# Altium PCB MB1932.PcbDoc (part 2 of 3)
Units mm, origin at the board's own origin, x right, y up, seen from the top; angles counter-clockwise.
Board outline 70 x 82.5 mm, 2 copper layers (Top Layer, Bottom Layer), stack 1.543 mm thick; 185 components, 150 nets, 679 pads, 649 vias.
Unrouted connection lines stored in the file: 108.
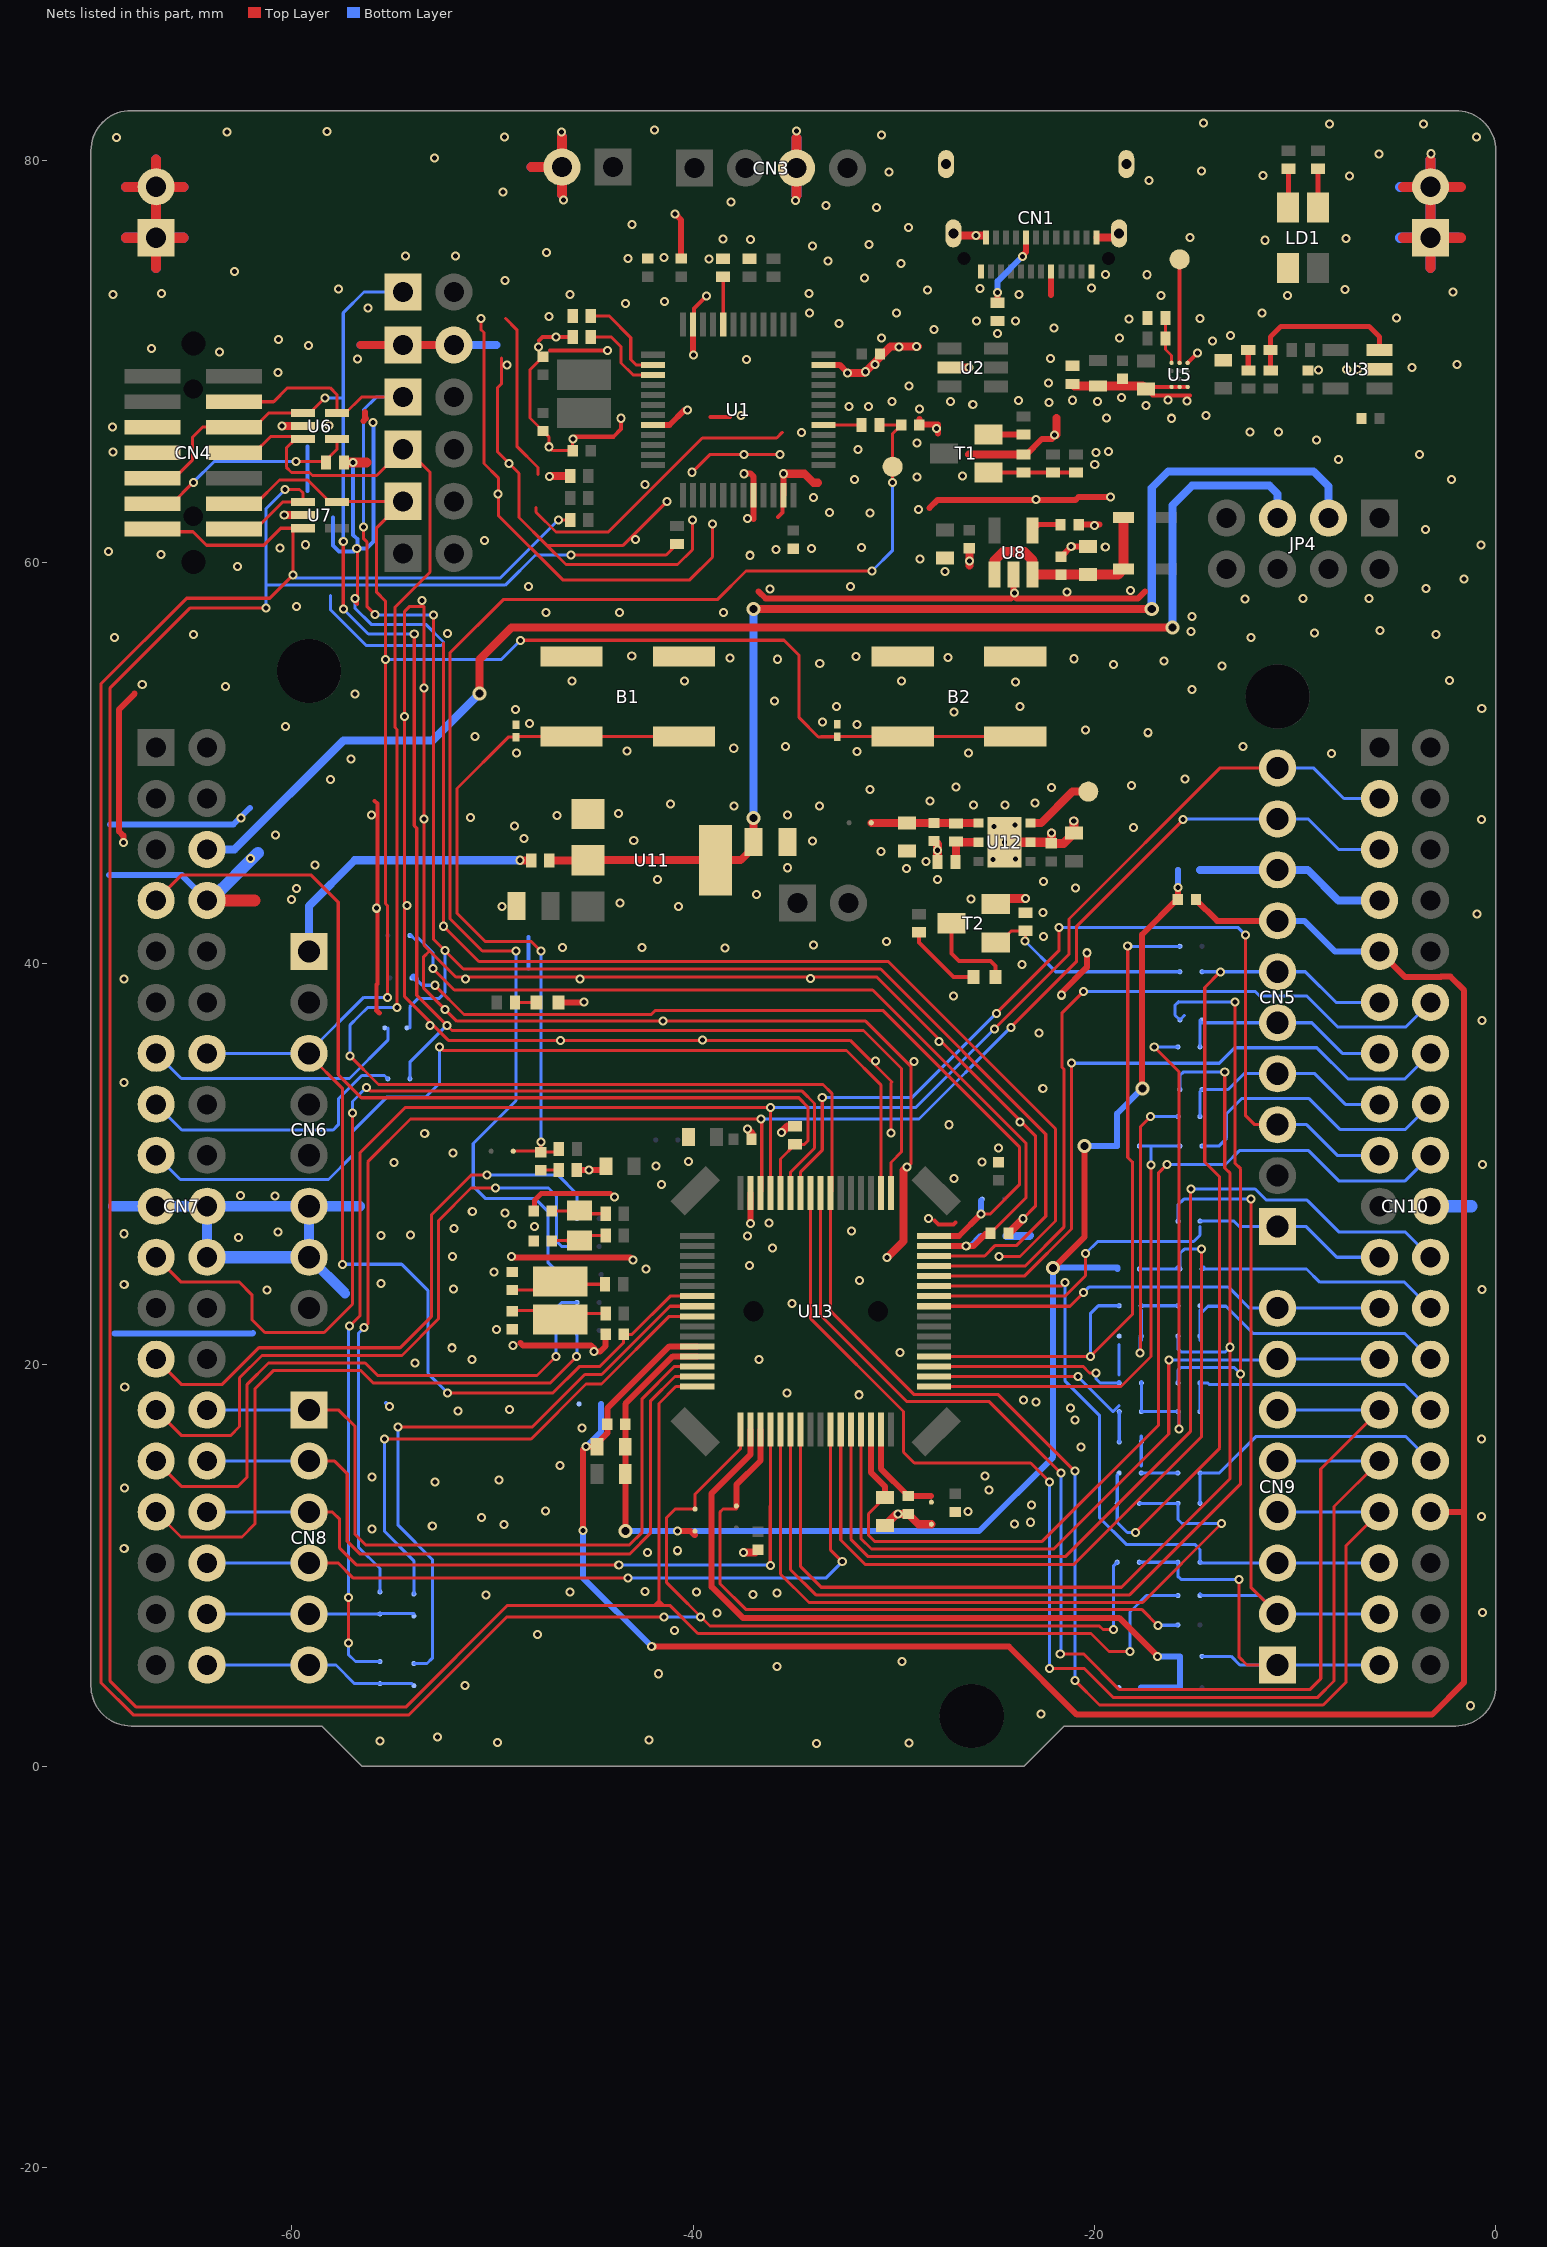
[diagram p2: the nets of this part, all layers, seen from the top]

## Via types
v1: diameter 0.45, hole 0.25, Top Layer to Bottom Layer, tented both sides, 618 vias
v2: diameter 0.7, hole 0.4, Top Layer to Bottom Layer, tented both sides, 28 vias
v3: diameter 0.5, hole 0.3, Top Layer to Bottom Layer, tented both sides, 3 vias

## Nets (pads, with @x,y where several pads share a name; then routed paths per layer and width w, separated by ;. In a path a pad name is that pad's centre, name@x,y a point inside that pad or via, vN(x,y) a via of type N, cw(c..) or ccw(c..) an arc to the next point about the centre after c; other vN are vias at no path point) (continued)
5V_VIN: C22.2 JP4.3 R26.1 U11.2 U11.4 | length 59.3
  Top Layer w0.4: R26.1@-47.165,45.139 -45.237,45.139 -45.232,45.144 U11.4@-38.887,45.144 -37.624,45.144 -36.981,45.786 C22.2@-36.981,46.043 C22.2@-36.981,46.043 v2(-36.982,47.252) ; v2(-36.981,57.666) v2(-17.141,57.666)
  Bottom Layer w0.4: v2(-36.982,47.252) v2(-36.981,57.666) v2(-36.981,57.666) ; v2(-17.141,57.666) -17.141,63.699 -16.318,64.522 -9.074,64.522 -8.33,63.777 JP4.3@-8.33,62.19
AGND: C26.1 C38.1 C39.2 CN5.7 CN10.9 CN10.32 SB36.2 U13.12 | length 116.3
  Top Layer w0.3: v1(-45.485,11.738) -45.474,11.749 -45.474,15.78 v1(-45.328,15.926) C39.2@-44.783,15.926 ; C39.2@-44.776,15.919 -44.776,16.089 -44.272,16.593 C38.1@-44.272,17.037 -44.272,17.825 -41.18,20.918 U13.12@-39.788,20.918 ; v1(-42.056,5.962) -24.266,5.962 -20.876,2.572 -3.176,2.572 -1.571,4.176 -1.571,12.66 ; C26.1@-14.941,43.181 -13.885,42.124 CN5.7@-10.87,42.124 ; CN10.9@-5.79,40.6 -4.525,39.335 -2.726,39.335 -2.721,39.34 -2.257,39.34 -1.571,38.654 -1.571,12.66 ; CN10.32@-3.25,12.66 -1.571,12.66
  Bottom Layer w0.3: v1(-45.485,11.738) -45.485,9.391 v1(-42.056,5.962) ; v1(-45.328,15.926) -44.576,16.678 SB36.2@-44.576,18.05 ; CN5.7@-10.87,42.124 -9.537,42.124 -8.013,40.6 CN10.9@-5.79,40.6
AVDD: C26.2 C38.2 C39.1 R38.2 SB8.1 SB9.2 SB21.2 SB26.2 U13.13 | length 71
  Top Layer w0.3: v2(-43.374,11.71) -43.374,14.473 -43.413,14.512 R38.2@-43.376,14.548 -43.372,14.552 C38.2@-43.372,17.037 -43.372,18.05 -41.004,20.418 U13.13@-39.788,20.418 ; v1(-40.776,11.718) -40.128,11.718 -39.92,11.509 -39.912,11.517 ; v2(-22.054,24.834) -22.023,24.834 -20.495,26.362 v2(-20.495,30.897) ; v2(-17.609,33.775) -17.62,33.786 -17.62,41.441 C26.2@-15.841,43.22 ; C26.2@-15.841,43.181 C26.2@-15.841,43.22 ; v1(-15.841,43.772) C26.2@-15.841,43.22
  Bottom Layer w0.3: v2@-43.374,11.718 v1(-40.776,11.718) -25.739,11.718 -22.055,15.402 -22.055,23.861 -22.056,23.863 -22.056,24.833 v2(-22.054,24.834) ; v2@-22.021,24.855 -18.859,24.855 SB26.2@-18.859,24.776 ; v2@-20.56,30.897 SB21.2@-18.861,30.897 -18.861,32.522 v2(-17.609,33.775) ; v2@-20.56,30.897 v2(-20.495,30.897) ; v1(-15.841,43.772) SB9.2@-15.841,44.662
BOOT0: CN7.7 R31.1 U13.60 | length 47.9
  Top Layer w0.152: CN7.7@-66.75,43.14 -65.493,44.397 -59.023,44.397 -57.677,43.051 -57.677,34.455 -56.529,33.306 -34.731,33.306 -34.275,32.85 -34.275,31.15 -34.44,30.985 R31.1@-34.91,30.985 -35.638,30.257 U13.60@-35.638,28.568
E5V: CN7.6 JP4.5 | length 66.8
  Top Layer w0.4: v2(-50.632,53.458) -50.632,55.149 -49.041,56.74 v2(-16.102,56.74)
  Bottom Layer w0.4: CN7.6@-64.21,45.68 -62.856,45.68 -57.423,51.113 -52.977,51.113 v2(-50.632,53.458) ; v2(-16.102,56.74) -16.102,62.82 -16.113,62.83 -15.127,63.816 -11.284,63.816 -10.87,63.402 JP4.5@-10.87,62.19
GND: B1.1 B1.2 B2.1 B2.2 C1.2 C2.2 C3.2 C4.1 C5.1 C6.2 C7.2 C9.1 C10.2 C11.1 C12.1 C13.1 C14.1 C15.1 C16.1 C17.2 C18.1 C19.1 C20.1 C21.1 C22.1 C23.1 C24.1 C25.1 C27.1 C28.1 C29.1 C31.2 C32.1 C33.2 C34.1 C35.1 C36.1 C37.1 C40.1 C41.2 C42.2 C43.1 CN1.A1 CN1.A12 CN1.B1 CN1.B12 CN1.SH1 CN1.SH2 CN1.SH3 CN1.SH4 CN3.3 CN4.5 CN4.7 CN6.6 CN6.7 CN7.8 CN7.19 CN7.20 CN7.22 CN10.20 JP1.2 JP2.1 JP2.2 JP3.1 JP3.2 JP11.1 JP11.2 LD1.3 LD3.2 R3.2 R4.1 R5.2 R7.2 R8.2 R9.1 R12.2 R15.1 R19.1 R21.2 R27.1 R29.2 R31.2 R33.2 SB5.2 SB6.2 SB36.1 SB54.2 T2.2 U1.8 U1.20 U1.23 U1.35 U1.47 U2.2 U3.2 U4.2 U5.A1 U5.A4 U5.B4 U5.C4 U6.2 U7.2 U8.2 U9.2 U10.2 U11.1 U12.2 U12.EP U13.63 | length 587
  Top Layer w0.152: v1(-56.85,58.192) -56.85,58.018 -56.729,57.896 v1@-56.729,60.617 ; -53.126,40.621 -53.435,40.312 -53.435,38.795 -51.765,37.125 -31.397,37.125 -29.13,34.858 -29.13,30.027 -29.297,29.86 v1(-29.338,29.86) ; -52.435,55.97 v1(-52.435,41.852) -50.674,40.092 -30.269,40.092 -21.933,31.755 -21.933,27.17 -23.705,25.398 v1(-24.757,25.398) ; v1@-50.572,72.144 v1(-50.572,72.135) -50.572,71.589 -50.418,71.435 -50.418,64.911 -49.702,64.195 -49.702,62.319 -46.496,59.113 -40.16,59.113 -39.027,60.245 v1(-39.027,61.898) ; -49.538,70.155 -49.538,68.894 -49.739,68.692 -49.739,65.494 -48.667,64.423 -48.667,62.217 -47.283,60.832 ; -49.338,72.14 -48.78,71.582 -48.78,65.769 -47.723,64.711 -47.723,64.357 ; -47.82,62.725 -47.82,62.488 -46.827,61.495 -44.219,61.495 -39.535,66.179 -35.831,66.179 -35.548,66.463 ; C4.1@-47.473,70.232 -48.12,69.584 -48.12,67.179 C10.2@-47.473,66.532 -47.182,66.242 v1(-47.182,65.745) -46.985,65.548 C13.1@-45.996,65.548 -45.996,66.119 v1(-45.98,66.135) ; v1@-47.278,64.265 v1(-47.144,64.265) ; v1(-41.287,63.023) -43.478,60.832 -47.283,60.832 ; v1(-40.04,64.475) -39.145,65.37 v1(-35.655,65.37) ; v1(-40.023,62.092) -40.023,60.62 -40.769,59.874 -46.324,59.874 -47.283,60.832 ; v1(-30.125,31.552) -30.125,34.049 -30.087,34.087 -32.168,36.167 -52.195,36.167 -54.369,38.342 -54.369,57.544 -54.116,57.796 -53.406,57.796 -53.406,40.909 -51.818,39.32 -30.84,39.32 -22.94,31.42 -22.94,27.898 v1(-23.56,27.277)
  Top Layer w0.2: -55.86,48.097 -55.722,47.96 -55.722,38.976 -55.768,38.93 ; -55.76,37.657 -55.76,38.95 ; -47.673,71.042 -47.503,71.212 R8.2@-46.118,71.212 ; -47.118,70.552 v1(-44.271,70.552) ; v1(-45.98,66.135) -45.871,66.244 -43.969,66.244 -43.588,66.625 -43.588,67.166 v1(-43.593,67.166) ; U1.47@-39.993,71.83 -39.955,71.868 -39.955,72.635 v1(-39.331,73.259) ; -39.12,67.225 -38.168,67.225 ; -35.767,62.233 -35.532,62.468 -35.532,63.291 U1.23@-35.493,63.33 ; -27.965,27.183 -27.77,26.987 -27.025,26.987 -26.925,27.087 ; C7.2@-18.601,69.131 -18.253,68.783 -18.226,68.783 ; U5.A4@-15.353,68.726 -17.534,68.726 -17.107,68.3 -15.228,68.3 ; U5.A1@-15.353,69.926 v1(-14.853,70.426)
  Top Layer w0.25: C32.1@-47.901,27.694 -47.901,28.197 -47.572,28.525 -44.103,28.525 v1@-43.945,28.368
  Top Layer w0.254: -55.76,37.657 -55.625,37.523
  Top Layer w0.3: v1(-68.387,46.017) -68.387,46.368 -68.594,46.575 -68.594,52.663 -67.818,53.439 ; -56.428,67.024 -56.299,67.152 -56.348,67.201 -56.348,67.468 ; v1(-49.033,25.395) -49.004,25.366 -48.898,25.366 -48.878,25.345 -48.872,25.351 -43.119,25.351 v1(-42.996,25.228) ; -48.607,21.095 -48.474,20.962 -45.077,20.962 -44.943,20.828 v1(-44.943,20.663) -44.625,20.663 -44.351,20.936 C37.1@-44.351,21.517 ; C32.1@-47.935,27.66 C32.1@-47.901,27.694 ; LD3.2@-46.706,38.06 v1@-45.467,38.06 ; R33.2@-45.79,29.697 -44.536,29.697 C31.2@-44.34,29.893 ; v1@-43.945,28.368 v1(-43.904,28.368) ; U1.8@-41.993,66.83 -41.173,66.83 -40.418,67.585 v1(-40.271,67.585) ; v1(-40.893,77.351) -40.588,77.046 C1.2@-40.588,75.122 ; v1@-39.993,70.328 U1.47@-39.993,71.83 ; v1@-37.457,64.415 -37.138,64.415 -36.993,64.271 -36.993,62.136 ; v1@-37.345,31.77 -37.323,31.748 v1(-37.295,31.748) ; v1(-37.138,27.03) U13.63@-37.138,28.568 ; -36.725,58.53 -36.389,58.194 -24.155,58.194 v1@-24.023,58.326 ; U1.23@-35.493,63.33 v1@-35.492,64.38 ; v1(-35.492,64.4) v1@-35.492,64.38 ; v1@-35.378,64.38 v1@-35.492,64.38 ; U1.35@-33.493,69.83 -32.697,69.83 -32.313,69.445 v1(-32.313,69.417) ; -28.726,67.131 -28.726,66.845 -27.791,66.845 -27.791,66.401 ; -28.216,62.697 -27.811,63.103 -20.93,63.103 -20.79,63.242 v1(-19.202,63.242) ; U8.2@-24.023,59.373 v1@-24.023,58.326 ; R19.1@-23.423,65.322 -22.611,66.135 -22.105,66.135 ; C19.1@-21.657,60.269 v1(-21.153,60.773) C18.1@-20.311,60.773 ; v1(-21.628,38.415) -21.628,38.55 -20.375,39.802 v1(-20.375,40.531) ; C14.1@-20.782,61.862 -19.758,61.862 ; -17.474,58.535 -17.815,58.194 -23.89,58.194 v1@-24.023,58.326
  Top Layer w0.4: v1(-60.469,66.777) U6.2@-59.438,66.777 ; v1(-60.367,62.335) U7.2@-59.438,62.334 ; -56.57,70.818 JP11.1@-54.455,70.818 JP11.2@-51.915,70.818 ; v1(-47.144,64.265) -47.144,64.278 R21.2@-46.118,64.278 ; v1(-37.484,10.643) -36.9,10.643 C43.1@-36.76,10.783 ; v1(-37.295,31.748) -37.082,31.535 C28.1@-37.082,31.24 ; v1(-35.598,31.582) -35.295,31.885 R31.2@-34.91,31.885 ; v1(-35.492,64.4) -34.45,64.4 -34.001,63.951 -33.767,63.951 ; v1(-32.313,69.417) -31.471,69.417 -30.151,70.737 v1@-28.777,70.737 ; C41.2@-30.369,11.993 C41.2@-30.438,11.993 -29.865,12.566 v1(-29.796,12.566) -29.277,12.566 -28.766,12.055 SB6.2@-28.123,12.055 ; v1(-30.324,25.345) -29.503,26.166 -29.503,29.041 -29.503,29.694 v1(-29.338,29.86) ; U2.2@-27.21,69.693 v1(-26.249,69.693) v1@-26.243,69.687 ; CN1.SH2@-27.03,76.381 -26.921,76.272 CN1.B1@-25.465,76.272 ; -26.245,65.36 R19.1@-23.54,65.36 ; v1@-26.232,59.838 C16.1@-26.232,60.683 ; C33.2@-24.28,26.55 -23.56,27.27 v1(-23.56,27.277) ; v1@-21.897,66.343 -21.897,67.168 ; CN1.B12@-19.84,76.171 -18.98,76.171 CN1.SH1@-18.77,76.381
  Top Layer w0.45: C21.1@-27.985,46.099 -27.817,45.931 R27.1@-27.817,45.055 ; T2.2@-24.914,42.952 -24.627,43.239 v1(-23.435,43.239) ; v1(-24.48,46.038) U12.2@-23.18,46.038 -22.203,46.038 C24.1@-22.148,45.984 -21.527,45.984 C23.1@-21.018,46.493 -21.018,47.093 v1(-21.028,47.102) ; C24.1@-22.143,45.989 v1(-22.143,46.508) ; R12.2@-21.087,68.878 -20.992,68.783 -18.253,68.783 ; -18.226,68.783 -17.591,68.783 C6.2@-17.534,68.726
  Top Layer w0.5: -68.261,76.16 JP2.1@-66.75,76.16 ; -68.261,78.7 JP2.2@-66.75,78.7 ; -66.75,74.649 JP2.1@-66.75,76.16 ; -66.75,80.062 JP2.2@-66.75,78.7 ; -65.388,76.16 JP2.1@-66.75,76.16 ; -65.388,78.7 JP2.2@-66.75,78.7 ; R15.1@-57.392,64.955 -56.275,64.955 ; -48.044,79.68 JP1.2@-46.533,79.68 ; -46.533,78.317 JP1.2@-46.533,79.68 ; -46.533,81.191 JP1.2@-46.533,79.68 ; -34.84,78.267 -34.84,81.141 ; -4.612,76.16 JP3.1@-3.25,76.16 ; -4.612,78.7 JP3.2@-3.25,78.7 ; -3.25,74.649 JP3.1@-3.25,76.16 ; -3.25,80.062 JP3.2@-3.25,78.7 ; -1.739,76.16 JP3.1@-3.25,76.16 ; -1.739,78.7 JP3.2@-3.25,78.7 ; JP2.1@-66.75,76.16 JP2.2@-66.75,78.7 ; JP3.1@-3.25,76.16 JP3.2@-3.25,78.7
  Top Layer w0.6: CN7.8@-64.21,43.14 -61.856,43.14
  Bottom Layer w0.152: -58.063,58.335 -58.063,57.62 -56.287,55.845 -52.56,55.845 -52.435,55.97 -52.435,56.018 -53.316,56.899 -56.036,56.899 -56.85,57.712 v1(-56.85,58.192)
  Bottom Layer w0.2: -59.197,63.552 -59.197,65.758 ; -57.927,62.21 -57.93,62.207 -57.93,60.824 -57.636,60.53 v1@-56.898,60.53 ; v1@-56.933,64.962 -56.933,61.353 -56.73,61.15 v1@-56.73,60.587 ; v1(-56.755,60.672) -56.278,60.672 -55.927,61.023 -55.927,66.937 v1@-55.938,66.947 ; -55.294,18.095 v1(-55.114,17.915) ; -48.2,39.746 -48.2,41.329
  Bottom Layer w0.254: -62.735,44.45 -62.669,44.516
  Bottom Layer w0.3: -69.092,44.4 -65.47,44.4 CN7.8@-64.21,43.14 ; -69.05,46.93 -69.047,46.933 -62.895,46.933 -62.081,47.746 ; -68.831,21.567 -61.94,21.567 -61.933,21.575 ; v1@-37.34,31.77 -37.317,31.748 v1(-37.295,31.748)
  Bottom Layer w0.4: -56.57,70.818 JP11.1@-54.455,70.818 JP11.2@-51.915,70.818 -49.8,70.818 ; SB5.2@-24.387,26.422 -23.235,26.422 -23.213,26.445
  Bottom Layer w0.5: -68.891,27.9 CN7.20@-64.21,27.9 ; -68.261,76.16 JP2.1@-66.75,76.16 ; -68.261,78.7 JP2.2@-66.75,78.7 ; -66.75,74.649 JP2.1@-66.75,76.16 ; -66.75,80.062 JP2.2@-66.75,78.7 ; -65.388,76.16 JP2.1@-66.75,76.16 ; -65.388,78.7 JP2.2@-66.75,78.7 ; CN7.22@-64.21,25.36 CN7.20@-64.21,27.9 ; -57.334,23.564 CN6.7@-59.13,25.36 CN6.6@-59.13,27.9 ; -56.59,27.9 CN6.6@-59.13,27.9 ; -48.044,79.68 JP1.2@-46.533,79.68 ; -46.533,78.317 JP1.2@-46.533,79.68 ; -46.533,81.191 JP1.2@-46.533,79.68 ; -34.84,78.267 -34.84,81.141 ; -4.761,76.16 JP3.1@-3.25,76.16 ; -4.761,78.7 JP3.2@-3.25,78.7 ; -3.25,74.649 JP3.1@-3.25,76.16 ; -3.25,80.062 JP3.2@-3.25,78.7 ; -1.888,76.16 JP3.1@-3.25,76.16 ; -1.888,78.7 JP3.2@-3.25,78.7 ; JP2.1@-66.75,76.16 JP2.2@-66.75,78.7 ; CN7.20@-64.21,27.9 CN6.6@-59.13,27.9 ; JP3.1@-3.25,76.16 JP3.2@-3.25,78.7
  Bottom Layer w0.6: CN7.22@-64.21,25.36 CN6.7@-59.13,25.36 ; CN7.8@-64.21,43.14 -64.045,43.14 -62.735,44.45 ; -62.669,44.516 -61.678,45.507 ; CN10.20@-3.25,27.9 -1.205,27.9
  other v1: -33.847,1.118 -49.74,1.169 -29.237,1.164 -55.585,1.248 -42.193,1.314 -52.729,1.459 -22.656,2.607 -1.266,3.011 -51.373,4.028 -41.729,4.606 -35.805,4.976 -29.595,5.225 -47.759,6.564 -40.918,6.749 -38.802,7.631 -0.669,7.661 -50.316,8.527 -37.014,8.545 -35.823,8.629 -39.821,8.672 -46.125,8.69 -42.391,8.693 -42.266,10.643 -40.768,10.735 -68.341,10.841 -55.991,11.814 -52.993,11.977 -49.422,12.038 -23.987,12.066 -23.178,12.155 -50.54,12.401 -0.702,12.452 -26.294,12.688 -47.35,12.718 -23.133,13.008 -25.244,13.773 -68.323,13.871 -52.867,14.165 -49.656,14.255 -55.996,14.405 -25.45,14.448 -46.626,14.982 -20.664,15.914 -0.702,16.313 -45.539,16.861 -20.974,17.26 -51.72,17.7 -49.155,17.765 -21.188,17.857 -22.9,18.157 -23.54,18.256 -31.718,18.507 -35.32,18.583 -68.316,18.893 -53.849,20.1 -36.707,20.257 -51.022,20.262 -29.684,20.623 -52.013,20.849 -48.975,20.957 -49.781,21.755 -35.079,23.051 -61.236,23.734 -0.687,23.752 -51.927,23.783 -68.341,23.998 -55.541,24.062 -31.706,24.197 -49.905,24.613 -42.342,24.776 -37.179,24.949 -51.977,25.398 -36.049,25.81 -62.638,26.335 -37.294,26.412 -55.556,26.45 -54.078,26.466 -68.346,26.53 -60.69,26.627 -32.104,26.668 -51.916,26.787 -47.907,26.902 -49.023,27.003 -36.212,27.07 -28.272,27.285 -49.369,27.555 -51,27.641 -60.828,28.407 -62.547,28.443 -41.58,28.988 -26.987,29.285 -45.19,29.697 -41.832,29.905 -0.669,29.983 -54.898,30.07 -25.6,30.105 -40.225,30.12 -51.958,30.548 -24.787,30.8 -53.368,31.528 -27.253,31.961 -23.71,32.087 -22.572,33.762 -68.346,34.056 -28.99,35.123 -30.915,35.147 -27.745,36.113 -46.605,36.165 -39.538,36.177 -22.762,36.533 -53.098,36.9 -41.485,37.143 -0.687,37.161 -52.348,37.695 -45.432,38.068 -27.019,38.38 -51.333,39.228 -45.642,39.228 -68.359,39.235 -34.135,39.238 -23.603,39.95 -38.411,40.763 -46.496,40.79 -42.546,40.783 -34.007,40.92 -30.349,41.085 -22.534,41.347 -0.931,42.459 -22.564,42.541 -55.768,42.75 -40.73,42.827 -49.515,42.843 -54.257,42.882 -43.648,43.01 -60,43.18 -26.143,43.209 -36.825,43.427 -59.751,43.734 -20.934,43.754 -22.541,44.082 -41.775,44.174 -27.817,44.174 -29.364,44.735 -35.285,44.767 -58.835,44.903 -28.399,45.073 -25.041,45.182 -23.938,45.192 -62.045,45.225 -30.641,45.576 -27.817,45.639 -34.04,46.099 -42.952,46.133 -48.41,46.226 -60.815,46.41 -18.06,46.772 -24.99,46.831 -48.898,46.859 -23.959,46.889 -0.72,47.163 -53.406,47.192 -62.515,47.258 -51.088,47.275 -56.028,47.385 -46.771,47.367 -35.292,47.403 -43.707,47.465 -37.961,47.844 -33.687,47.844 -26.013,47.892 -24.464,47.885 -41.129,47.941 -22.966,47.996 -28.201,48.085 -31.185,48.677 -26.901,48.781 -22.14,48.774 -18.142,48.858 -58.057,49.173 -15.493,49.18 -57.042,50.18 -8.175,50.458 -26.27,50.478 -48.8,50.488 -31.835,50.549 -43.28,50.585 -37.969,50.722 -12.6,50.813 -35.394,50.818 -50.868,51.303 -17.327,51.495 -20.436,51.639 -60.309,51.806 -31.835,51.913 -48.156,51.953 -33.55,52.028 -54.37,52.305 -26.985,52.523 -48.847,52.654 -0.697,52.693 -32.859,52.81 -23.705,52.797 -35.945,53.076 -56.832,53.42 -15.139,53.648 -53.409,53.727 -63.293,53.811 -67.444,53.902 -23.941,54.026 -46.019,54.062 -40.42,54.082 -29.61,54.067 -2.295,54.108 -13.651,54.819 -19.044,54.893 -33.684,54.948 -16.542,55.06 -35.795,55.157 -21.025,55.182 -38.15,55.225 -27.294,55.235 -31.889,55.289 -43.052,55.324 -68.818,56.234 -12.199,56.231 -64.901,56.384 -2.973,56.386 -52.225,56.437 -9.031,56.467 -15.191,56.528 -5.767,56.579 -15.142,57.298 -47.317,57.497 -43.657,57.497 -38.477,57.497 -59.748,57.79 -53.511,58.075 -12.504,58.156 -9.604,58.176 -6.325,58.181 -23.992,58.461 -21.355,58.504 -18.198,58.591 -36.168,58.659 -3.476,58.672 -48.205,58.773 -32.153,58.779 -1.589,59.155 -27.446,59.536 -62.69,59.778 -26.232,60.046 -28.683,60.158 -37.164,60.338 -66.517,60.377 -69.13,60.536 -35.859,60.63 -34.102,60.67 -60.583,60.705 -31.607,60.727 -19.458,60.76 -59.303,60.862 -0.728,60.859 -50.387,61.068 -42.865,61.128 -3.509,61.618 -19.999,61.819 -37.276,62.177 -31.185,62.448 -33.21,62.475 -28.77,62.607 -22.92,63.107 -33.992,63.224 -49.715,63.382 -42.391,63.867 -31.948,64.125 -2.196,64.118 -28.837,64.24 -26.568,64.295 -37.457,64.4 -19.981,64.862 -49.157,64.912 -56.948,64.962 -7.845,65.106 -3.804,65.36 -37.447,65.37 -19.927,65.467 -68.897,65.48 -19.302,65.52 -31.788,65.617 -28.833,65.932 -8.932,66.088 -21.979,66.325 -34.586,66.465 -12.237,66.485 -10.832,66.49 -27.868,66.65 -68.915,66.73 -58.135,66.804 -55.945,66.947 -16.155,67.165 -19.395,67.182 -14.44,67.295 -37.613,67.305 -28.703,67.622 -31.257,67.755 -32.217,67.76 -17.42,67.81 -26.06,67.847 -22.263,67.947 -30.087,68.006 -27.17,67.995 -19.835,68.003 -15.388,68.033 -23.785,68.04 -21.087,68.062 -16.325,68.077 -18.655,68.21 -29.248,68.762 -22.297,68.917 -60.679,69.457 -31.407,69.483 -8.828,69.562 -7.425,69.604 -6.891,69.606 -4.184,69.685 -49.275,69.825 -30.925,69.845 -1.929,69.846 -56.713,70.11 -37.337,70.097 -22.197,70.148 -39.984,70.318 -63.606,70.463 -66.98,70.653 -47.69,70.717 -29.725,70.72 -28.857,70.737 -59.166,70.78 -14.112,71.005 -60.644,71.085 -30.605,71.16 -18.743,71.156 -46.832,71.212 -13.227,71.29 -24.825,71.385 -28,71.58 -22.01,71.657 -32.718,71.887 -25.88,72.023 -23.94,72.023 -18.286,72.118 -14.735,72.134 -4.953,72.169 -47.169,72.231 -29.857,72.402 -34.198,72.418 -11.651,72.415 -56.197,72.658 -43.367,72.894 -41.419,72.988 -16.692,73.29 -10.37,73.287 -68.901,73.33 -46.125,73.33 -23.753,73.337 -66.476,73.386 -34.228,73.386 -2.12,73.466 -28.323,73.562 -7.507,73.582 -57.665,73.608 -25.692,73.638 -20.15,73.66 -49.368,74.03 -31.445,74.16 -19.45,74.317 -17.38,74.316 -62.836,74.489 -29.63,74.868 -33.275,74.994 -43.237,75.119 -39.205,75.11 -41.457,75.172 -51.84,75.243 -54.325,75.253 -47.289,75.413 -34.04,75.745 -31.23,75.835 -11.508,76.036 -37.144,76.084 -38.495,76.096 -7.459,76.117 -15.234,76.173 -25.887,76.272 -29.268,76.68 -43.047,76.825 -30.86,77.658 -33.383,77.772 -38.099,77.943 -46.45,78.042 -34.893,78.027 -49.468,78.446 -17.281,79.012 -11.586,79.256 -7.286,79.241 -30.245,79.433 -14.655,79.477 -52.88,80.132 -5.828,80.343 -3.226,80.345 -68.736,81.161 -49.394,81.169 -0.964,81.187 -30.598,81.283 -63.222,81.438 -58.248,81.442 -46.549,81.428 -34.84,81.471 -41.929,81.522 -8.292,81.822 -3.596,81.837 -14.553,81.867
GNDDetect: CN4.11 R15.2 U6.4 | length 10.9
  Top Layer w0.152: CN4.11@-66.928,62.909 -65.961,62.909 v1(-64.9,63.97) ; v1(-59.785,65) -58.432,65 -58.395,64.962 -57.738,65.62 U6.4@-57.738,66.127
  Bottom Layer w0.152: v1(-64.9,63.97) -63.87,65 v1(-59.785,65)
MCU.MCO: C11.2 R17.2 SB27.1 TP2.1 | length 70.1
  Top Layer w0.152: v1(-48.817,40.615) -50.5,40.615 -52.105,42.22 -52.105,55.48 -49.462,58.123 -38.792,58.123 -37.359,59.556 v1(-31.078,59.556) ; R17.2@-30.705,66.83 -30.702,66.833 C11.2@-29.625,66.833 -29.625,66.823 -30.055,66.393 v1@-30.055,63.967
  Bottom Layer w0.152: v1(-48.817,40.615) -48.817,33.165 -50.951,31.031 -50.951,28.895 -50.332,28.276 -47.86,28.276 -47.235,27.651 -47.235,25.11 -46.626,24.5 SB27.1@-45.676,24.5 ; v1(-31.078,59.556) -30.049,60.586 -30.063,60.599 v1(-30.063,63.967)
MCU.VCP_RX: CN4.13 R23.2 SB8.2 SB45.2 U7.3 U13.17 | length 156.2
  Top Layer w0.152: CN4.13@-66.928,61.639 -66.798,61.509 -64.911,61.509 -64.239,60.838 -61.39,60.838 -60.544,61.684 U7.3@-59.773,61.684 ; U7.3@-59.438,61.684 U7.3@-59.773,61.684 ; v1(-46.707,62.102) R23.2@-46.117,62.102 ; v1(-41.444,7.43) -49.282,7.43 -54.154,2.559 -67.899,2.559 -69.506,4.166 -69.506,53.925 -65.233,58.198 -61.09,58.198 v1(-59.942,59.345) -59.942,61.515 U7.3@-59.773,61.684 ; U13.17@-37.638,16.768 -37.638,15.813 -39.9,13.552 SB8.2@-39.9,12.81 -40.89,12.81 -41.312,12.388 -41.312,9.145 -39.154,6.987 -19.75,6.987 -19.571,6.808 v1(-19.036,6.808)
  Bottom Layer w0.152: v1(-59.942,59.345) -59.804,59.206 -49.603,59.206 v1(-46.707,62.102) ; v1(-41.444,7.43) v1(-39.628,7.43) ; v1(-19.036,6.808) -19.036,9.986 SB45.2@-18.863,10.16
MCU.VCP_TX: CN4.14 R24.2 SB48.2 U7.1 U13.16 | length 164
  Top Layer w0.152: CN4.14@-62.864,61.639 -61.796,61.639 -60.451,62.984 U7.1@-59.438,62.984 -59.438,63.447 -59.604,63.614 -59.605,63.612 v1(-60.323,63.612) ; v1(-61.269,57.718) -65.05,57.718 -69.06,53.707 -69.06,4.259 -67.741,2.94 -54.311,2.94 -49.239,8.012 -41.16,8.012 -39.758,6.61 -20.172,6.61 -19.275,5.713 v1(-18.221,5.713) ; v1(-46.085,60.353) -41.337,60.353 R24.2@-40.79,60.9 ; -41.918,8.022 -41.698,8.242 ; -41.698,8.032 -41.698,8.242 ; -41.478,8.022 -41.698,8.242 ; U13.16@-39.788,18.918 -40.856,18.918 -41.698,18.075 -41.698,8.242
  Bottom Layer w0.152: v1(-61.269,57.718) -61.269,58.847 ; v1(-60.323,63.612) -61.269,62.666 -61.269,58.847 ; v1(-46.085,60.353) -47.853,60.353 -49.358,58.847 -52.37,58.847 -52.373,58.85 -53.052,58.85 -53.055,58.847 -61.269,58.847 ; v1(-18.221,5.713) -18.221,7.687 -17.408,8.499 SB48.2@-15.839,8.499
NetB1_3: B1.3 B1.4 C30.2 R32.1 SB3.1 U10.1 | length 35.9
  Top Layer w0.152: U10.1@-48.819,51.275 -49.207,51.275 -51.764,48.718 -51.764,42.501 -50.356,41.094 -48.059,41.094 v1(-47.58,40.615) ; U10.1@-48.794,51.3 B1.4@-40.455,51.3 ; -48.782,30.647 C30.2@-47.641,30.647 ; v1(-47.586,31.1) -47.586,30.647 C30.2@-47.641,30.647 ; R32.1@-46.685,30.76 -46.848,30.597 C30.2@-47.591,30.597 C30.2@-47.641,30.647 ; R32.1@-46.685,30.76 R32.1@-46.684,30.966
  Bottom Layer w0.152: v1(-47.586,31.1) -47.588,31.103 -47.58,31.111 v1(-47.58,40.615)
NetC14_2: C14.2 U8.4 | length 1.5
  Top Layer w0.254: U8.4@-23.073,61.573 -22.783,61.862 C14.2@-21.682,61.862
NetC18_2: C18.2 C19.2 D1.2 D2.2 U8.1 U8.3 | length 10.9
  Top Layer w0.5: U8.1@-24.973,59.373 -24.972,60.071 -24.549,60.495 -23.493,60.495 -23.073,60.074 U8.3@-23.073,59.373 -23.069,59.369 C19.2@-21.657,59.369 -21.653,59.373 -18.821,59.373 D2.2@-18.544,59.65 D1.2@-18.544,62.215
NetC20_2: C20.2 C21.2 R25.2 SB1.1 U12.4 | length 5.3
  Top Layer w0.4: SB1.1@-31.102,46.991 C20.2@-29.335,46.991 ; C20.2@-29.327,46.999 C21.2@-27.985,46.999 -25.791,46.999 U12.4@-25.78,46.988
  Top Layer w0.5: C20.2@-29.335,46.991 C20.2@-29.327,46.999
NetC30_1: C30.1 R33.1 | length 0.9
  Top Layer w0.152: C30.1@-47.591,29.697 R33.1@-46.69,29.697
NetC32_2: C32.2 R34.1 X2.2 | length 2.8
  Top Layer w0.152: C32.2@-47.035,27.66 -45.703,27.66 X2.2@-45.665,27.697 -45.494,27.527 R34.1@-44.348,27.527
NetC33_1: C33.1 SB5.1 SB10.1 U13.47 | length 45
  Top Layer w0.152: v1(-52.955,39.74) -51.895,38.68 -31.047,38.68 -23.397,31.03 -23.397,28.332 C33.1@-25.18,26.55 C33.1@-25.382,26.55
  Top Layer w0.3: U13.47@-27.988,25.918 -26.015,25.918 C33.1@-25.382,26.55
  Bottom Layer w0.152: SB10.1@-54.088,41.425 -53.803,41.139 -53.682,41.26 -52.955,40.532 v1(-52.955,39.74)
  Bottom Layer w0.3: v1(-26.385,25.917) -26.16,25.917 -25.655,26.422 SB5.1@-25.487,26.422
NetC34_2: C34.2 R35.1 X2.1 | length 3.2
  Top Layer w0.152: C34.2@-47.035,26.173 -47.011,26.197 X2.1@-46.287,26.197 ; -46.311,26.173 X2.1@-46.287,26.197 ; X2.1@-46.044,26.441 X2.1@-46.287,26.197 ; R35.1@-44.348,26.441 -45.422,26.441 X2.1@-45.665,26.197 X2.1@-46.287,26.197
NetC35_2: C35.2 R36.1 X3.2 | length 4.9
  Top Layer w0.152: C35.2@-49.004,23.73 -47.035,23.73 X3.2@-46.615,24.15 -46.478,24.013 R36.1@-44.38,24.013
NetC36_2: C36.2 R37.1 X3.1 | length 5
  Top Layer w0.152: C36.2@-49.004,22.7 -47.064,22.7 X3.1@-46.615,22.25 -46.3,22.565 R37.1@-44.348,22.565
NetC42_1: C42.1 SB6.1 U13.31 | length 5
  Top Layer w0.3: U13.31@-30.638,16.768 -30.638,14.827 C42.1@-29.271,13.46 -28.156,13.46 -28.147,13.451
NetCN1_A5: CN1.A5 R12.1 | length 1.2
  Top Layer w0.3: -22.15,73.31 CN1.A5@-22.15,74.471
NetCN1_B5: CN1.B5 R3.1 | length 3.9
  Top Layer w0.3: R3.1@-24.833,72.917 -24.823,72.927 v1(-24.823,73.435) ; v1(-23.584,75.231) -23.587,75.234 -23.587,75.27 -23.4,75.457 CN1.B5@-23.4,76.171
  Bottom Layer w0.3: v1(-24.823,73.435) -24.823,73.992 v1(-23.584,75.231) v1@-23.604,75.231
NetCN5_4: CN5.4 CN10.15 SB18.2 SB19.1 | length 11.2
  Bottom Layer w0.152: SB19.1@-14.739,32.37 -14.739,33.617 SB18.2@-14.639,33.717 -13.334,33.717 -12.546,34.504 CN5.4@-10.87,34.504 -9.016,34.504 -7.492,32.98 CN10.15@-5.79,32.98
NetCN5_5: CN5.5 CN10.13 SB14.2 SB16.1 | length 10.8
  Bottom Layer w0.152: SB16.1@-14.737,35.837 SB14.2@-14.737,37.184 ; -14.637,37.044 CN5.5@-10.87,37.044 -9.168,37.044 -7.644,35.52 CN10.13@-5.79,35.52
NetCN5_6: CN5.6 CN10.11 SB12.2 SB41.1 SB43.2 | length 43.3
  Top Layer w0.152: v1(-17.962,11.641) -13.756,15.848 -13.756,29.358 -14.5,30.102 -14.5,38.804 v1(-13.725,39.579)
  Bottom Layer w0.152: -18.861,14.513 -18.861,12.145 -18.357,11.641 v1(-17.962,11.641) ; SB12.2@-14.64,39.584 CN5.6@-10.87,39.584 -9.488,39.584 -7.964,38.06 CN10.11@-5.79,38.06
NetCN5_8: CN5.8 CN10.7 SB9.1 | length 9.6
  Bottom Layer w0.4: SB9.1@-14.739,44.664 CN5.8@-10.87,44.664 -9.369,44.664 -7.845,43.14 CN10.7@-5.79,43.14
NetCN6_1: CN6.1 R26.2 | length 14.3
  Top Layer w0.4: v1(-48.629,45.141) -48.626,45.139 R26.2@-48.065,45.139
  Bottom Layer w0.4: CN6.1@-59.13,40.6 -59.13,42.868 -56.857,45.142 v1(-48.629,45.141)
NetCN7_13: CN7.13 SB15.2 | length 13.5
  Bottom Layer w0.152: CN7.13@-66.75,35.52 -65.498,34.268 -57.117,34.268 -55.209,36.176 -55.209,36.79
NetCN7_15: CN7.15 SB17.2 | length 14
  Bottom Layer w0.152: CN7.15@-66.75,32.98 -65.47,31.7 -57.933,31.7 -57.675,31.958 -57.675,33.244 -56.504,34.415 -55.374,34.415 SB17.2@-55.209,34.25
NetCN7_25: CN7.25 SB22.2 | length 30.4
  Top Layer w0.152: CN7.25@-66.75,20.28 -65.478,19.007 -63.476,19.007 -61.636,20.848 -54.591,20.848 -53.04,22.399 -53.04,27.46 -51.037,29.462 v1(-50.263,29.462)
  Bottom Layer w0.152: v1(-50.263,29.462) -46.745,29.462 -45.776,28.493 SB22.2@-45.776,27.283
NetCN7_27: CN7.27 SB24.2 | length 33.4
  Top Layer w0.152: CN7.27@-66.75,17.74 -65.48,16.47 -63.047,16.47 -62.595,16.922 -62.595,19.35 -61.478,20.467 -54.505,20.467 -52.685,22.287 -52.685,27.18 -51.058,28.807 v1(-49.841,28.807)
  Bottom Layer w0.152: v1(-49.841,28.807) -47.2,28.807 -46.796,28.403 -46.796,26.147 -46.54,25.891 SB24.2@-45.776,25.891
NetCN7_29: CN7.29 SB28.2 | length 29.9
  Top Layer w0.152: CN7.29@-66.75,15.2 -65.493,13.943 -62.676,13.943 -62.214,14.405 -62.214,19.026 -61.153,20.087 -56.338,20.087 -55.716,19.465 -47.774,19.465 v1(-46.829,20.41)
  Bottom Layer w0.152: v1(-46.829,20.41) -46.829,22.82 -46.541,23.108 SB28.2@-45.776,23.108
NetCN7_31: CN7.31 SB31.2 | length 31
  Top Layer w0.152: CN7.31@-66.75,12.66 -65.513,11.423 -62.473,11.423 -61.833,12.063 -61.833,18.794 -60.921,19.706 -56.542,19.706 -55.92,19.084 -47.124,19.084 v1(-45.798,20.41)
  Bottom Layer w0.152: v1(-45.798,20.41) -45.785,20.422 -45.785,21.479 -45.8,21.494 -45.8,21.62 -45.795,21.625 -45.795,21.697 SB31.2@-45.776,21.717
NetCN7_36: CN7.36 CN8.5 SB46.2 SB47.1 | length 10.3
  Bottom Layer w0.152: CN7.36@-64.21,7.58 CN8.5@-59.13,7.58 SB47.1@-55.602,7.58 ; SB47.1@-55.599,7.583 -55.585,7.597 SB46.2@-53.898,7.597
NetCN7_38: CN7.38 CN8.6 SB51.1 SB52.2 | length 10.6
  Bottom Layer w0.152: CN7.38@-64.21,5.04 CN8.6@-59.13,5.04 -57.794,5.04 -56.866,4.112 SB51.1@-55.599,4.112 -54.009,4.112
NetCN10_26: CN10.26 SB29.1 SB32.1 | length 14.3
  Bottom Layer w0.152: -14.741,21.208 -14.741,22.721 ; -14.74,22.515 -14.339,22.917 -13.441,22.917 -12.074,21.55 -4.52,21.55 CN10.26@-3.25,20.28
NetCN10_28: CN10.28 SB34.1 SB37.1 | length 13.6
  Bottom Layer w0.152: SB37.1@-14.739,17.666 SB34.1@-14.739,19.098 ; SB34.1@-14.739,19.179 SB34.1@-14.739,19.098 ; CN10.28@-3.25,17.74 -4.52,19.01 -14.256,19.01 -14.344,19.098 SB34.1@-14.739,19.098
NetCN10_30: CN10.30 SB40.1 SB42.1 | length 14.3
  Bottom Layer w0.152: SB42.1@-14.738,13.097 -14.738,14.607 SB40.1@-14.741,14.61 -13.771,14.61 -11.962,16.419 -4.469,16.419 CN10.30@-3.25,15.2
NetLD1_1: LD1.1 R1.1 | length 1.9
  Top Layer w0.254: LD1.1@-10.337,77.673 R1.1@-10.337,79.596
NetLD1_2: LD1.2 R2.2 | length 1.9
  Top Layer w0.254: LD1.2@-8.863,77.673 R2.2@-8.863,79.596
NetLD2_1: LD2.1 R13.1 | length 1
  Top Layer w0.254: R13.1@-12.332,69.554 LD2.1@-12.332,70.571
NetLD2_2: LD2.2 R14.1 U3.3 | length 8.2
  Top Layer w0.254: R14.1@-11.232,69.568 LD2.2@-11.232,70.571 -11.232,71.216 -10.704,71.745 -6.312,71.745 -5.791,71.224 U3.3@-5.791,70.556
NetLD3_1: LD3.1 R30.2 | length 1.1
  Top Layer w0.152: R30.2@-48.876,38.06 LD3.1@-47.806,38.06
NetLD4_1: LD4.1 R28.1 | length 3.9
  Top Layer w0.2: R28.1@-28.742,41.552 -28.742,41.042 -27.03,39.33 LD4.1@-26.025,39.33
NetLD4_2: LD4.2 T2.3 | length 4.5
  Top Layer w0.2: T2.3@-27.114,42.002 -27.114,40.502 -26.734,40.122 -25.175,40.122 -24.925,39.872 LD4.2@-24.925,39.33
NetR4_2: R4.2 U1.44 | length 2.4
  Top Layer w0.152: U1.44@-38.493,71.83 R4.2@-38.493,74.203
NetR7_1: R7.1 U1.2 | length 4.9
  Top Layer w0.152: R7.1@-45.218,72.268 -44.188,72.268 -43.103,71.183 -43.103,70.094 -42.838,69.83 U1.2@-41.993,69.83
NetR8_1: R8.1 U1.3 | length 4.5
  Top Layer w0.152: R8.1@-45.218,71.212 -44.068,71.212 -43.585,70.729 -43.585,69.922 -42.993,69.33 U1.3@-41.993,69.33
NetR9_2: R9.2 R10.1 U5.C1 | length 2.4
  Top Layer w0.152: R9.2@-16.452,72.17 R10.1@-16.452,71.129 -16.452,70.595 -16.153,70.295 U5.C1@-16.153,69.926
NetR16_2: R16.2 T1.2 | length 1.7
  Top Layer w0.3: T1.2@-25.284,66.366 R16.2@-23.556,66.366
NetR17_1: R17.1 U1.29 | length 2.1
  Top Layer w0.152: U1.29@-33.493,66.83 R17.1@-31.605,66.83 R17.1@-31.478,66.702
NetR18_1: R18.1 R19.2 R20.1 T1.1 | length 4.4
  Top Layer w0.203: T1.1@-25.284,64.466 -20.917,64.466 R18.1@-20.911,64.46
NetR25_1: R25.1 R27.2 U12.5 | length 2.2
  Top Layer w0.4: R27.2@-26.917,45.055 -26.905,45.067 R25.1@-26.905,46.073 -26.87,46.038 U12.5@-25.78,46.038
NetR29_1: R29.1 SB12.1 T2.1 | length 10.7
  Top Layer w0.152: T2.1@-24.914,41.052 -24.7,41.052 -24.127,41.626 R29.1@-23.443,41.626 -23.443,41.136 v1(-23.461,41.118) -23.377,41.034 v1@-23.359,41.052
  Bottom Layer w0.152: v1(-23.461,41.118) -21.927,39.584 SB12.1@-15.74,39.584
NetSB4_2: SB4.2 SB13.2 U13.48 | length 41.8
  Top Layer w0.152: v1(-52.867,38.913) -51.41,37.455 -42.08,37.455 -41.87,37.665 -30.543,37.665 -23.741,30.864 -23.741,28.968 -25.205,27.505 v1(-25.658,27.505)
  Top Layer w0.3: U13.48@-27.988,26.418 -26.745,26.418 v1(-25.658,27.505)
  Bottom Layer w0.152: -53.793,39.216 -53.49,38.913 v1(-52.867,38.913)
  Bottom Layer w0.3: SB13.2@-53.933,39.355 -53.793,39.216 ; v1(-25.658,27.505) SB4.2@-25.658,28.185
NetSB7_2: SB7.2 SB49.2 U13.19 | length 32.6
  Top Layer w0.152: SB7.2@-37.84,12.968 -37.84,12.81 -38.505,12.81 -38.665,12.651 -38.665,9.106 -37.354,7.796 -17.619,7.796 -16.837,7.014 v1(-16.829,7.021)
  Top Layer w0.3: SB7.2@-37.84,12.968 -37.84,14.024 -36.638,15.226 U13.19@-36.638,16.768
  Bottom Layer w0.152: v1(-16.829,7.021) -15.855,7.021 SB49.2@-15.84,7.036
NetSB11_1: SB11.1 SB30.1 U13.36 | length 35.5
  Top Layer w0.152: U13.36@-27.988,20.418 v1(-20.204,20.418) -18.093,22.529 -18.093,30.086 -18.108,30.101 -18.338,30.331 v1(-18.338,40.859)
  Bottom Layer w0.152: v1(-20.204,20.418) -20.204,22.544 -19.806,22.942 SB30.1@-18.763,22.942 ; v1(-18.338,40.859) -18.333,40.854 SB11.1@-15.739,40.854
NetSB20_1: SB20.1 SB21.1 U13.33 | length 23.9
  Top Layer w0.152: U13.33@-27.988,18.918 -21.037,18.918 -21.032,18.913 -20.614,18.913 -20.61,18.918 -18.677,18.918 -17.178,20.416 v1@-17.178,29.96
  Bottom Layer w0.152: SB21.1@-17.761,30.897 -17.169,30.897 ; v1(-17.179,29.96) -17.179,30.887 -17.169,30.897 ; SB20.1@-15.739,30.897 -17.169,30.897
NetSB25_1: SB25.1 SB26.1 U13.27 | length 40.1
  Top Layer w0.152: U13.27@-32.638,16.768 -32.638,11.271 -31.426,10.059 -21.012,10.059 -14.662,16.409 v1(-14.662,25.764)
  Bottom Layer w0.152: SB26.1@-17.759,24.776 -15.884,24.776 -15.917,24.809 -15.736,24.99 ; SB25.1@-15.736,24.776 -15.736,24.99 ; v1(-14.662,25.764) -15.516,25.764 -15.736,25.544 -15.736,24.99
NetSB33_1: SB33.1 SB35.1 U13.35 | length 11.3
  Top Layer w0.152: U13.35@-27.988,19.918 -27.983,19.922 -20.57,19.922 -20.24,19.592 v1(-19.915,19.592)
  Bottom Layer w0.152: v1(-19.915,19.592) -19.915,19.3 -19.713,19.098 SB35.1@-18.762,19.098 ; SB35.1@-18.791,19.15 SB35.1@-18.762,19.179 ; -18.763,19.489 -18.763,21.002
NetSB38_1: SB38.1 SB39.1 U13.34 | length 11.6
  Top Layer w0.152: U13.34@-27.988,19.418 v1(-20.823,19.418)
  Bottom Layer w0.152: v1(-20.823,19.418) -19.072,17.666 -18.763,17.976 ; SB39.1@-18.762,16.153 SB38.1@-18.762,17.666
NetSB50_1: SB50.1 SB53.1 SB54.1 U13.18 | length 36.9
  Top Layer w0.152: -37.528,7.431 -37.489,7.392
  Top Layer w0.3: U13.18@-37.138,16.768 -37.138,15.525 -39.068,13.595 -39.068,8.939 -37.544,7.415 -37.52,7.391 -18.763,7.391 v1(-16.844,5.472)
  Bottom Layer w0.3: SB54.1@-17.673,3.912 SB53.1@-15.74,3.912 SB50.1@-15.74,5.474 -15.742,5.472 v1(-16.844,5.472)
NetTP1_1: TP1.1 U5.B1 | length 5.2
  Top Layer w0.203: U5.B1@-15.753,69.926 TP1.1@-15.753,75.082
NetTP3_1: TP3.1 U12.3 | length 3.5
  Top Layer w0.4: U12.3@-23.18,46.988 -22.663,46.988 -21.089,48.563 TP3.1@-20.304,48.563
NRST: B2.3 B2.4 C37.2 CN4.12 CN6.3 CN7.14 JP9.1 U7.5 U9.1 U13.7 | length 117.6
  Top Layer w0.152: CN4.12@-62.864,62.909 -61.784,62.909 -60.602,64.091 -59.204,64.091 -58.14,63.028 JP9.1@-54.455,63.028 -55.766,61.717 -55.766,58.491 -55.325,58.05 v1(-55.325,55.153) -55.325,48.057 -55.318,48.051 -55.318,42.978 -55.23,42.89 v1(-55.23,38.31) ; CN6.3@-59.13,35.52 -59.13,35.441 -57.471,33.783 v1(-57.471,25.009) ; v1(-52.232,18.6) -46.973,18.6 -45.651,19.922 -44.636,19.922 -43.46,21.098 -43.46,21.507 C37.2@-43.451,21.517 -43.042,21.517 -41.141,23.418 U13.7@-39.788,23.418 ; v1(-48.595,56.102) -35.469,56.102 -34.713,55.346 -34.713,52.243 -33.755,51.286 U9.1@-32.821,51.286 ; -33.63,51.3 B2.4@-23.945,51.3
  Bottom Layer w0.152: CN7.14@-64.21,35.52 CN6.3@-59.13,35.52 -59.13,35.585 -56.405,38.31 v1(-55.23,38.31) ; v1(-57.471,25.009) -54.515,25.009 -53.214,23.709 -53.214,19.582 v1(-52.232,18.6) ; v1(-55.325,55.153) -49.545,55.153 v1(-48.595,56.102)
PA0: CN7.28 CN8.1 U13.14 | length 37.9
  Top Layer w0.152: CN8.1@-59.13,17.74 -57.647,17.74 -56.844,16.937 -56.844,11.553 -56.311,11.019 -43.176,11.019 -42.536,11.659 -42.536,18.315 -40.933,19.918 U13.14@-39.788,19.918
  Bottom Layer w0.152: CN7.28@-64.21,17.74 CN8.1@-59.13,17.74
PA1: CN7.30 CN8.2 U13.15 | length 35.8
  Top Layer w0.152: CN8.2@-59.13,15.2 -57.858,15.2 -57.228,14.57 -57.228,11.202 -56.588,10.562 -43.167,10.562 -42.125,11.604 -42.125,18.187 -40.895,19.418 U13.15@-39.788,19.418
  Bottom Layer w0.152: CN7.30@-64.21,15.2 CN8.2@-59.13,15.2
PA2: CN9.2 CN10.35 SB23.2 SB48.1 | length 35.2
  Top Layer w0.152: v1@-12.206,28.335 v1(-12.206,28.253) -12.206,28.206 -12.205,28.205 -12.205,8.915 CN9.2@-10.87,7.58
  Bottom Layer w0.152: SB23.2@-15.839,27.156 -15.839,27.958 -15.544,28.253 v1(-12.206,28.253) ; SB48.1@-14.74,8.598 -14.652,8.51 -11.8,8.51 CN9.2@-10.87,7.58 CN10.35@-5.79,7.58
PA3: CN9.1 CN10.37 SB44.2 SB45.1 SB50.2 | length 20.7
  Top Layer w0.152: v1(-12.803,9.297) -12.803,6.973 -12.803,5.45 -12.393,5.04 CN9.1@-10.87,5.04
  Bottom Layer w0.152: SB45.1@-17.763,10.16 SB44.2@-15.84,10.16 -15.84,9.461 -15.676,9.297 v1(-12.803,9.297) ; SB50.2@-14.64,5.474 -13.183,5.474 -12.75,5.04 CN9.1@-10.87,5.04 CN10.37@-5.79,5.04
PA4: CN7.32 CN8.3 U13.20 | length 36.8
  Top Layer w0.152: CN8.3@-59.13,12.66 -57.962,12.66 -57.609,12.307 -57.609,10.864 -56.776,10.031 v1(-43.7,10.031) ; v1(-36.148,10.003) -36.15,10.006 -36.15,12.973 -36.138,12.985 U13.20@-36.138,16.768
  Bottom Layer w0.152: CN7.32@-64.21,12.66 CN8.3@-59.13,12.66 ; v1(-43.7,10.031) -36.175,10.031 v1(-36.148,10.003)
PA5: SB42.2 SB43.1 U13.21 | length 36.4
  Top Layer w0.152: U13.21@-35.638,16.768 -35.638,9.569 -34.223,8.154 -17.596,8.154 v1(-13.662,12.088)
  Bottom Layer w0.152: SB43.1@-17.761,13.097 SB42.2@-15.838,13.097 -15.838,12.294 -15.633,12.088 v1(-13.662,12.088)
PA6: SB14.1 SB34.2 U13.22 | length 64.5
  Top Layer w0.152: U13.22@-35.138,16.768 -35.138,9.793 -33.88,8.535 -18.244,8.535 -12.712,14.067 -12.712,29.764 -13,30.052 -13,38.079 v1(-12.994,38.085)
  Bottom Layer w0.152: SB34.2@-15.839,19.098 -15.839,19.723 -15.695,19.867 -13.025,19.867 v1(-12.709,19.551) ; -15.509,37.412 SB14.1@-15.737,37.184 -15.978,37.424 -15.978,37.915 -15.803,38.09 -15.798,38.085 v1(-12.994,38.085)
PA7: SB18.1 SB32.2 U13.23 | length 57.7
  Top Layer w0.152: U13.23@-34.638,16.768 -34.638,9.941 -33.613,8.916 -18.653,8.916 -13.232,14.336 -13.232,29.538 -13.504,29.81 v1(-13.504,34.58)
  Bottom Layer w0.152: SB32.2@-15.841,21.429 -15.841,20.801 -15.669,20.629 -13.493,20.629 v1(-13.248,20.874) ; SB18.1@-15.739,33.717 -15.739,34.413 -15.572,34.58 v1(-13.504,34.58)
PA8: CN9.8 CN10.23 U13.41 | length 23
  Top Layer w0.152: U13.41@-27.988,22.918 -21.219,22.918 v1(-20.545,23.592)
  Bottom Layer w0.152: v1(-20.545,23.592) -20.253,23.884 -13.331,23.884 -12.267,22.82 CN9.8@-10.87,22.82 CN10.23@-5.79,22.82
PA9: CN5.1 CN10.21 SB23.1 U13.42 | length 25.3
  Top Layer w0.152: U13.42@-27.988,23.418 -21.461,23.418 -20.438,24.441 v1(-20.438,25.545)
  Bottom Layer w0.152: v1(-20.438,25.545) -19.839,26.145 -15.053,26.145 -14.739,26.459 -14.739,26.884 ; SB23.1@-14.739,27.156 -13.042,27.156 -12.77,26.884 CN5.1@-10.87,26.884 -9.44,26.884 -7.916,25.36 CN10.21@-5.79,25.36
PA10: CN9.3 CN10.33 SB44.1 U13.43 | length 34.3
  Top Layer w0.152: U13.43@-27.988,23.918 -21.647,23.918 v1(-21.453,24.112)
  Bottom Layer w0.152: v1(-21.453,24.112) -21.453,19.184 -19.755,17.486 -19.755,12.393 -18.414,11.052 -14.998,11.052 -14.74,10.795 SB44.1@-14.74,10.16 ; SB44.1@-14.7,10.12 CN9.3@-10.87,10.12 CN10.33@-5.79,10.12
PA11: CN10.14 U13.44 | length 35.5
  Top Layer w0.152: U13.44@-27.988,24.418 -23.492,24.418 -21.142,26.768 v1(-21.142,35.035)
  Bottom Layer w0.152: v1(-21.142,35.035) -21.132,35.025 -13.773,35.025 -12.998,35.799 -8.914,35.799 -7.365,34.25 -4.52,34.25 CN10.14@-3.25,35.52
PA12: CN10.12 U13.45 | length 38
  Top Layer w0.152: U13.45@-27.988,24.918 -23.459,24.918 -21.52,26.856 -21.52,34.736 -21.621,34.837 -21.621,37.524 v1(-20.55,38.595)
  Bottom Layer w0.152: v1(-20.55,38.595) -11.971,38.595 -11.743,38.366 -9.409,38.366 -7.883,36.841 -4.469,36.841 CN10.12@-3.25,38.06
PA13: CN4.4 JP7.1 SB15.1 U6.5 U13.46 | length 92.5
  Top Layer w0.152: CN4.4@-62.864,67.989 -60.898,67.989 -60.207,68.68 -58.081,68.68 -57.738,68.336 U6.5@-57.738,67.427 ; U6.5@-57.519,67.427 -57.312,67.427 -56.522,68.217 JP7.1@-54.455,68.217 JP7.1@-54.254,68.217 ; v1(-56.43,61.743) -56.43,61.184 -56.251,61.005 -56.251,57.791 v1(-55.838,57.378) ; U13.46@-27.988,25.418 -25.47,25.418 -24.933,25.955 -23.867,25.955 -22.423,27.4 -22.423,31.495 -30.65,39.723 -51.445,39.723 -52.927,41.205 v1(-52.927,57.36) ; v1(-52.927,57.36) -53.025,57.36 -52.927,57.457 v1(-52.927,57.36)
  Bottom Layer w0.152: v1(-56.43,61.743) -56.43,67.575 -55.788,68.217 JP7.1@-54.455,68.217 JP7.1@-54.254,68.217 ; v1@-55.838,57.36 v1(-52.927,57.36) ; -54.109,36.79 -54.109,37.836 -53.685,38.26 -52.639,38.26 -52.358,38.541 v1(-52.358,40.648)
PA14: CN4.6 CN4.9 JP6.1 SB17.1 U6.1 U13.49 | length 87.8
  Top Layer w0.152: CN4.9@-66.928,64.179 -65.856,64.179 -64.932,65.103 -64.932,66.228 -64.441,66.719 -61.853,66.719 -61.145,67.427 U6.1@-59.438,67.427 -59.096,67.427 v1(-58.348,68.175) ; v1(-57.428,61.032) -57.428,57.663 v1(-57.425,57.66) ; v1(-53.89,56.413) -53.89,46.865 -53.765,46.74 -53.765,38.415 v1(-52.268,36.918) -52.01,36.66 -31.508,36.66 -29.609,34.761 -29.609,30.611 -30.138,30.082 U13.49@-30.138,28.568
  Bottom Layer w0.152: v1(-58.348,68.175) -57.428,68.175 ; v1(-57.428,61.032) -57.428,68.174 -57.428,72.42 -56.39,73.458 JP6.1@-54.455,73.458 JP6.1@-54.255,73.458 ; v1(-57.425,57.66) -56.178,56.413 v1(-53.89,56.413) ; SB17.1@-54.109,34.25 -54.109,35.081 v1@-52.27,36.92
PA15: CN7.17 U13.50 | length 47.3
  Top Layer w0.152: v1(-52.635,35.835) -52.462,35.662 -32.353,35.662 -30.638,33.948 U13.50@-30.638,28.568
  Bottom Layer w0.152: CN7.17@-66.75,30.44 -65.546,29.236 -58.158,29.236 -56.958,30.436 -56.958,31.64 -55.263,33.335 -53.333,33.335 -52.635,34.033 v1(-52.635,35.835)
PB0: CN7.34 CN8.4 U13.26 | length 39.1
  Top Layer w0.152: CN8.4@-59.13,10.12 -57.677,10.12 -56.928,9.371 v1(-43.242,9.371) ; U13.26@-33.138,16.768 -33.138,10.762 v1(-32.563,10.187)
  Bottom Layer w0.152: CN7.34@-64.21,10.12 CN8.4@-59.13,10.12 ; v1(-43.242,9.371) -33.38,9.371 v1(-32.563,10.187)
PB1: CN10.24 SB25.2 | length 12.3
  Bottom Layer w0.152: SB25.2@-14.549,24.863 SB25.2@-14.636,24.776 -9.427,24.776 -8.767,24.115 -4.546,24.115 CN10.24@-3.25,22.82
PB2: CN10.22 U13.28 | length 50.8
  Top Layer w0.152: U13.28@-32.138,16.768 -32.138,11.309 -31.268,10.44 -21.447,10.44 -15.219,16.668 -15.219,28.725 v1(-15.186,28.759)
  Bottom Layer w0.152: v1(-15.186,28.759) -11.988,28.759 -11.449,28.22 -9.427,28.22 -9.379,28.172 -9.371,28.179 -7.801,26.609 -4.499,26.609 CN10.22@-3.25,25.36
PB3: CN4.8 CN9.4 CN10.31 JP8.1 U6.3 U13.55 | length 136
  Top Layer w0.152: CN4.8@-62.864,65.449 -61.856,65.449 -61.054,66.25 -59.7,66.25 U6.3@-59.824,66.127 ; U6.3@-59.438,66.127 U6.3@-59.824,66.127 ; v1(-57.098,35.392) -55.671,33.966 -33.518,33.966 -33.081,33.529 -33.081,28.624 U13.55@-33.138,28.568 -33.138,22.672 -28.977,18.512 -24.787,18.512 v1(-20.972,14.697) ; v1(-54.745,37.795) -54.745,51.661 -54.849,51.765 -54.849,54.952 -54.846,54.954 -54.846,55.351 -54.848,55.352 -54.848,57.755 -53.108,59.495 -53.108,64.474 -54.355,65.721 JP8.1@-54.455,65.621 -55.765,64.31 -58.957,64.31 -59.111,64.465 -60.002,64.465 -60.264,64.726 -60.264,65.687 U6.3@-59.824,66.127 ; v1(-20.972,4.278) -19.745,3.051 -8.602,3.051 -7.456,4.197 -7.456,10.994 CN10.31@-5.79,12.66
  Bottom Layer w0.152: v1(-57.098,35.392) -57.098,36.918 -56.638,37.377 -56.64,37.378 -56.222,37.796 ; -56.221,37.795 v1(-54.745,37.795) ; v1(-20.972,4.278) v1(-20.972,14.697) ; CN9.4@-10.87,12.66 CN10.31@-5.79,12.66
PB4: CN9.6 CN10.27 U13.56 | length 64
  Top Layer w0.152: U13.56@-33.638,28.568 -33.638,22.453 -29.366,18.182 -25.262,18.182 -23.128,16.048 -23.114,16.048 v1(-21.666,14.601) ; v1(-21.701,5.589) -20.53,5.589 -18.754,3.813 -9.267,3.813 -8.721,4.359 -8.721,14.809 CN10.27@-5.79,17.74
  Bottom Layer w0.152: v1(-21.701,5.589) -21.666,5.623 v1(-21.666,14.601) ; CN9.6@-10.87,17.74 CN10.27@-5.79,17.74
PB5: CN9.5 CN10.29 U13.57 | length 64.1
  Top Layer w0.152: U13.57@-34.138,28.568 -34.138,22.298 -29.514,17.674 -29.514,15.65 -28.974,15.11 -23.178,15.11 v1(-22.239,14.171) ; v1(-22.239,4.862) -20.504,4.862 -19.074,3.432 -8.866,3.432 -8.056,4.242 -8.056,12.934 CN10.29@-5.79,15.2
  Bottom Layer w0.152: v1(-22.239,4.862) v1(-22.239,14.171) ; CN9.5@-10.87,15.2 CN10.29@-5.79,15.2
PB6: CN5.3 CN10.17 U13.58 | length 47.1
  Top Layer w0.152: U13.58@-34.638,28.568 -34.638,29.617 -33.56,30.695 v1(-33.56,33.328) ; v1(-24.885,37.513) -21.769,40.628 v1(-21.769,41.796) ; v1(-12.48,41.425) -12.48,32.434 -12.011,31.964 CN5.3@-10.87,31.964
  Bottom Layer w0.152: v1(-33.56,33.328) -29.07,33.328 v1(-24.885,37.513) ; v1(-21.769,41.796) -12.851,41.796 v1(-12.48,41.425) ; CN5.3@-10.87,31.964 -9.422,31.964 -7.898,30.44 CN10.17@-5.79,30.44
PB7: CN7.21 U13.59 | length 51.3
  Top Layer w0.152: CN7.21@-66.75,25.36 -65.526,24.136 -62.623,24.136 -61.983,23.496 -61.983,22.26 -61.333,21.61 -58.379,21.61 -56.967,23.022 ; -56.968,23.022 v1(-56.968,32.553) ; v1(-56.267,33.823) -56.081,33.636 -34.563,33.636 -33.945,33.018 -33.945,30.792 -35.138,29.6 U13.59@-35.138,28.568
  Bottom Layer w0.152: v1(-56.968,32.553) -56.968,33.122 v1(-56.267,33.823)
PB8: CN5.10 CN10.3 SB51.2 U13.61 | length 91.6
  Top Layer w0.152: v1(-57.177,8.395) -57.177,6.153 v1(-57.172,6.147) ; v1(-57.111,21.934) -56.586,22.458 -56.586,30.576 -54.343,32.82 v1(-36.138,32.82) U13.61@-36.138,28.568 ; v1(-24.987,36.73) -21.261,40.456 -21.261,42.213 -13.73,49.744 CN5.10@-10.87,49.744
  Bottom Layer w0.152: v1(-57.177,8.395) -57.177,21.867 v1(-57.111,21.934) ; v1(-57.172,6.147) -57.172,5.563 -56.82,5.212 SB51.2@-55.599,5.212 ; v1(-36.138,32.82) -28.897,32.82 v1(-24.987,36.73) ; CN5.10@-10.87,49.744 -9.092,49.744 -7.568,48.22 CN10.3@-5.79,48.22
PB9: CN5.9 CN10.5 SB47.2 U13.62 | length 84.9
  Top Layer w0.152: v1(-56.384,21.857) -56.206,22.036 -56.206,30.115 -54.076,32.245 v1(-36.622,32.245) -36.573,32.196 -36.573,28.632 U13.62@-36.638,28.568 ; v1(-24.164,36.818) -20.88,40.102 -20.88,41.859 v1@-15.574,47.165
  Bottom Layer w0.152: v1(-56.384,21.857) -56.664,21.578 -56.664,10.916 -55.599,9.852 SB47.2@-55.599,8.683 ; v1(-36.622,32.245) -28.737,32.245 v1(-24.164,36.818) ; v1(-15.584,47.176) -15.559,47.201 -15.416,47.201 -15.413,47.204 CN5.9@-10.87,47.204 -9.351,47.204 -7.827,45.68 CN10.5@-5.79,45.68
PB10: CN9.7 CN10.25 U13.29 | length 37.7
  Top Layer w0.152: U13.29@-31.638,16.768 -31.638,11.348 -31.111,10.821 -22.023,10.821 -16.293,16.551 v1(-16.293,20.229)
  Bottom Layer w0.152: v1@-16.392,20.248 -10.87,20.248 CN9.7@-10.87,20.28 CN10.25@-5.79,20.28
PB11: C41.1 CN10.18 U13.30 | length 50.4
  Top Layer w0.152: C41.1@-30.564,13.268 -31.257,12.574 -31.257,11.506 -30.953,11.202 -22.6,11.202 -16.797,17.004 -16.797,29.57 v1(-16.387,29.98)
  Top Layer w0.3: U13.30@-31.138,16.768 -31.138,14.646 -30.438,13.946 C41.1@-30.438,13.393
  Bottom Layer w0.152: v1(-16.387,29.98) -13.466,29.98 -12.778,30.669 -9.321,30.669 -7.801,29.149 -4.541,29.149 CN10.18@-3.25,30.44
PB12: CN10.16 SB20.2 | length 14.2
  Bottom Layer w0.152: SB20.2@-14.639,30.897 -13.801,30.897 -13.407,31.291 -13.407,32.526 -12.673,33.259 -9.295,33.259 -7.771,31.735 -4.495,31.735 CN10.16@-3.25,32.98
PB13: SB39.2 SB40.2 SB41.2 | length 3.3
  Bottom Layer w0.152: -17.665,14.95 -17.665,16.46 ; SB39.2@-17.665,16.15 SB39.2@-17.662,16.153 ; SB41.2@-17.663,14.61 SB40.2@-15.841,14.61
PB14: SB16.2 SB35.2 SB37.2 SB38.2 | length 24.9
  Top Layer w0.152: v1(-17.017,35.84) -15.789,34.612 v1(-15.789,16.811)
  Bottom Layer w0.152: SB35.2@-17.662,19.179 SB38.2@-17.662,17.666 SB37.2@-15.839,17.666 -15.789,17.615 v1(-15.789,16.811) ; v1@-17.014,35.837 SB16.2@-15.837,35.837
PB15: SB19.2 SB29.2 SB30.2 SB33.2 | length 17.7
  Top Layer w0.152: v1(-17.726,20.582) -17.712,20.597 -17.712,31.853 v1(-17.195,32.37)
  Bottom Layer w0.152: v1(-17.726,20.582) -17.726,21.135 -17.731,21.14 ; SB33.2@-17.663,21.429 -17.731,21.362 -17.731,21.14 ; SB30.2@-17.663,22.942 SB29.2@-15.841,22.942 ; -17.663,22.721 -17.663,21.208 -17.731,21.14 ; v1(-17.195,32.37) SB19.2@-15.839,32.37
PC0: SB52.1 U13.8 | length 30.7
  Top Layer w0.152: v1(-54.693,16.909) -47.997,16.909 -45.389,19.518 -44.551,19.518 -41.151,22.918 U13.8@-39.788,22.918
  Bottom Layer w0.152: v1(-54.693,16.909) -54.693,12.002 -52.988,10.298 -52.988,5.378 -53.255,5.112 SB52.1@-53.909,5.112
PC1: SB46.1 U13.9 | length 26.4
  Top Layer w0.152: v1(-55.366,16.305) -48.068,16.305 -48.065,16.302 -45.328,19.04 -44.562,19.04 -41.184,22.418 U13.9@-39.788,22.418
  Bottom Layer w0.152: v1(-55.366,16.305) -55.366,11.69 -53.909,10.233 SB46.1@-53.909,8.583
